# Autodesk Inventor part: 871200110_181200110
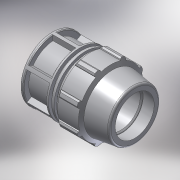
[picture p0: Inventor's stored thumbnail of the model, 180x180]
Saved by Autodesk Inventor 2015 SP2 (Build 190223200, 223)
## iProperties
Created: 2017-02
Part Number: 871200110_181200110
Material: PVC-Piping
Description: PLASSON END PLUG 110
Document SubType Name: Modeling
Designer: KIM
Mass: 92.6774 g
Surface Area: 199.44 cm^2
Volume: 66.1981 cm^3
Density: 1.4 g/cm^3
Appearance: Smooth - White
Author: Кирилл
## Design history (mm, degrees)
derived "87120.ipt"
feature "Solid1::87120.ipt"
tag "TaggingFeature1"
body "Solid1"
other parameters: "d4" = 33.42857, "d5" = 58.5, "d7" = 181, "d8" = 135.75, "d9" = 33.42857, "d11" = 6.68571, "d12" = 144.8, "d13" = 120 deg, "d14" = 143, "d15" = 8 deg, "d16" = 162.9, "d18" = 5.5, "d19" = 35 deg, "d20" = 17.5 deg, "d21" = 168.33, "d23" = 0, "d25" = 360 deg, "d27" = 3.62, "d34" = 9.05, "d36" = 0, "d42" = 58.5, "d43" = 5.43, "d46" = 3.3, "d53" = 2.2, "d55" = 360 deg, "d59" = 58.5, "d64" = 234, "d66" = 23.53, "d67" = 14.48, "d68" = 221, "d70" = 26.74286, "d71" = 6.68571, "d72" = 159.642, "d75" = 13.37143, "E_" = 181, "H_" = 234, "l_" = 221
